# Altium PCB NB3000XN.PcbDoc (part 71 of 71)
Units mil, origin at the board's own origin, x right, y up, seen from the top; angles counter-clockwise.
Board outline 9527.56 x 6929.77 mil, 6 copper layers (Top Layer, GND+SHIELD, MidLayer1, MidLayer2, P2 - 3V3+5V0, Bottom Layer), stack 62.375 mil thick; 832 components, 1027 nets, 4655 pads, 4981 vias.
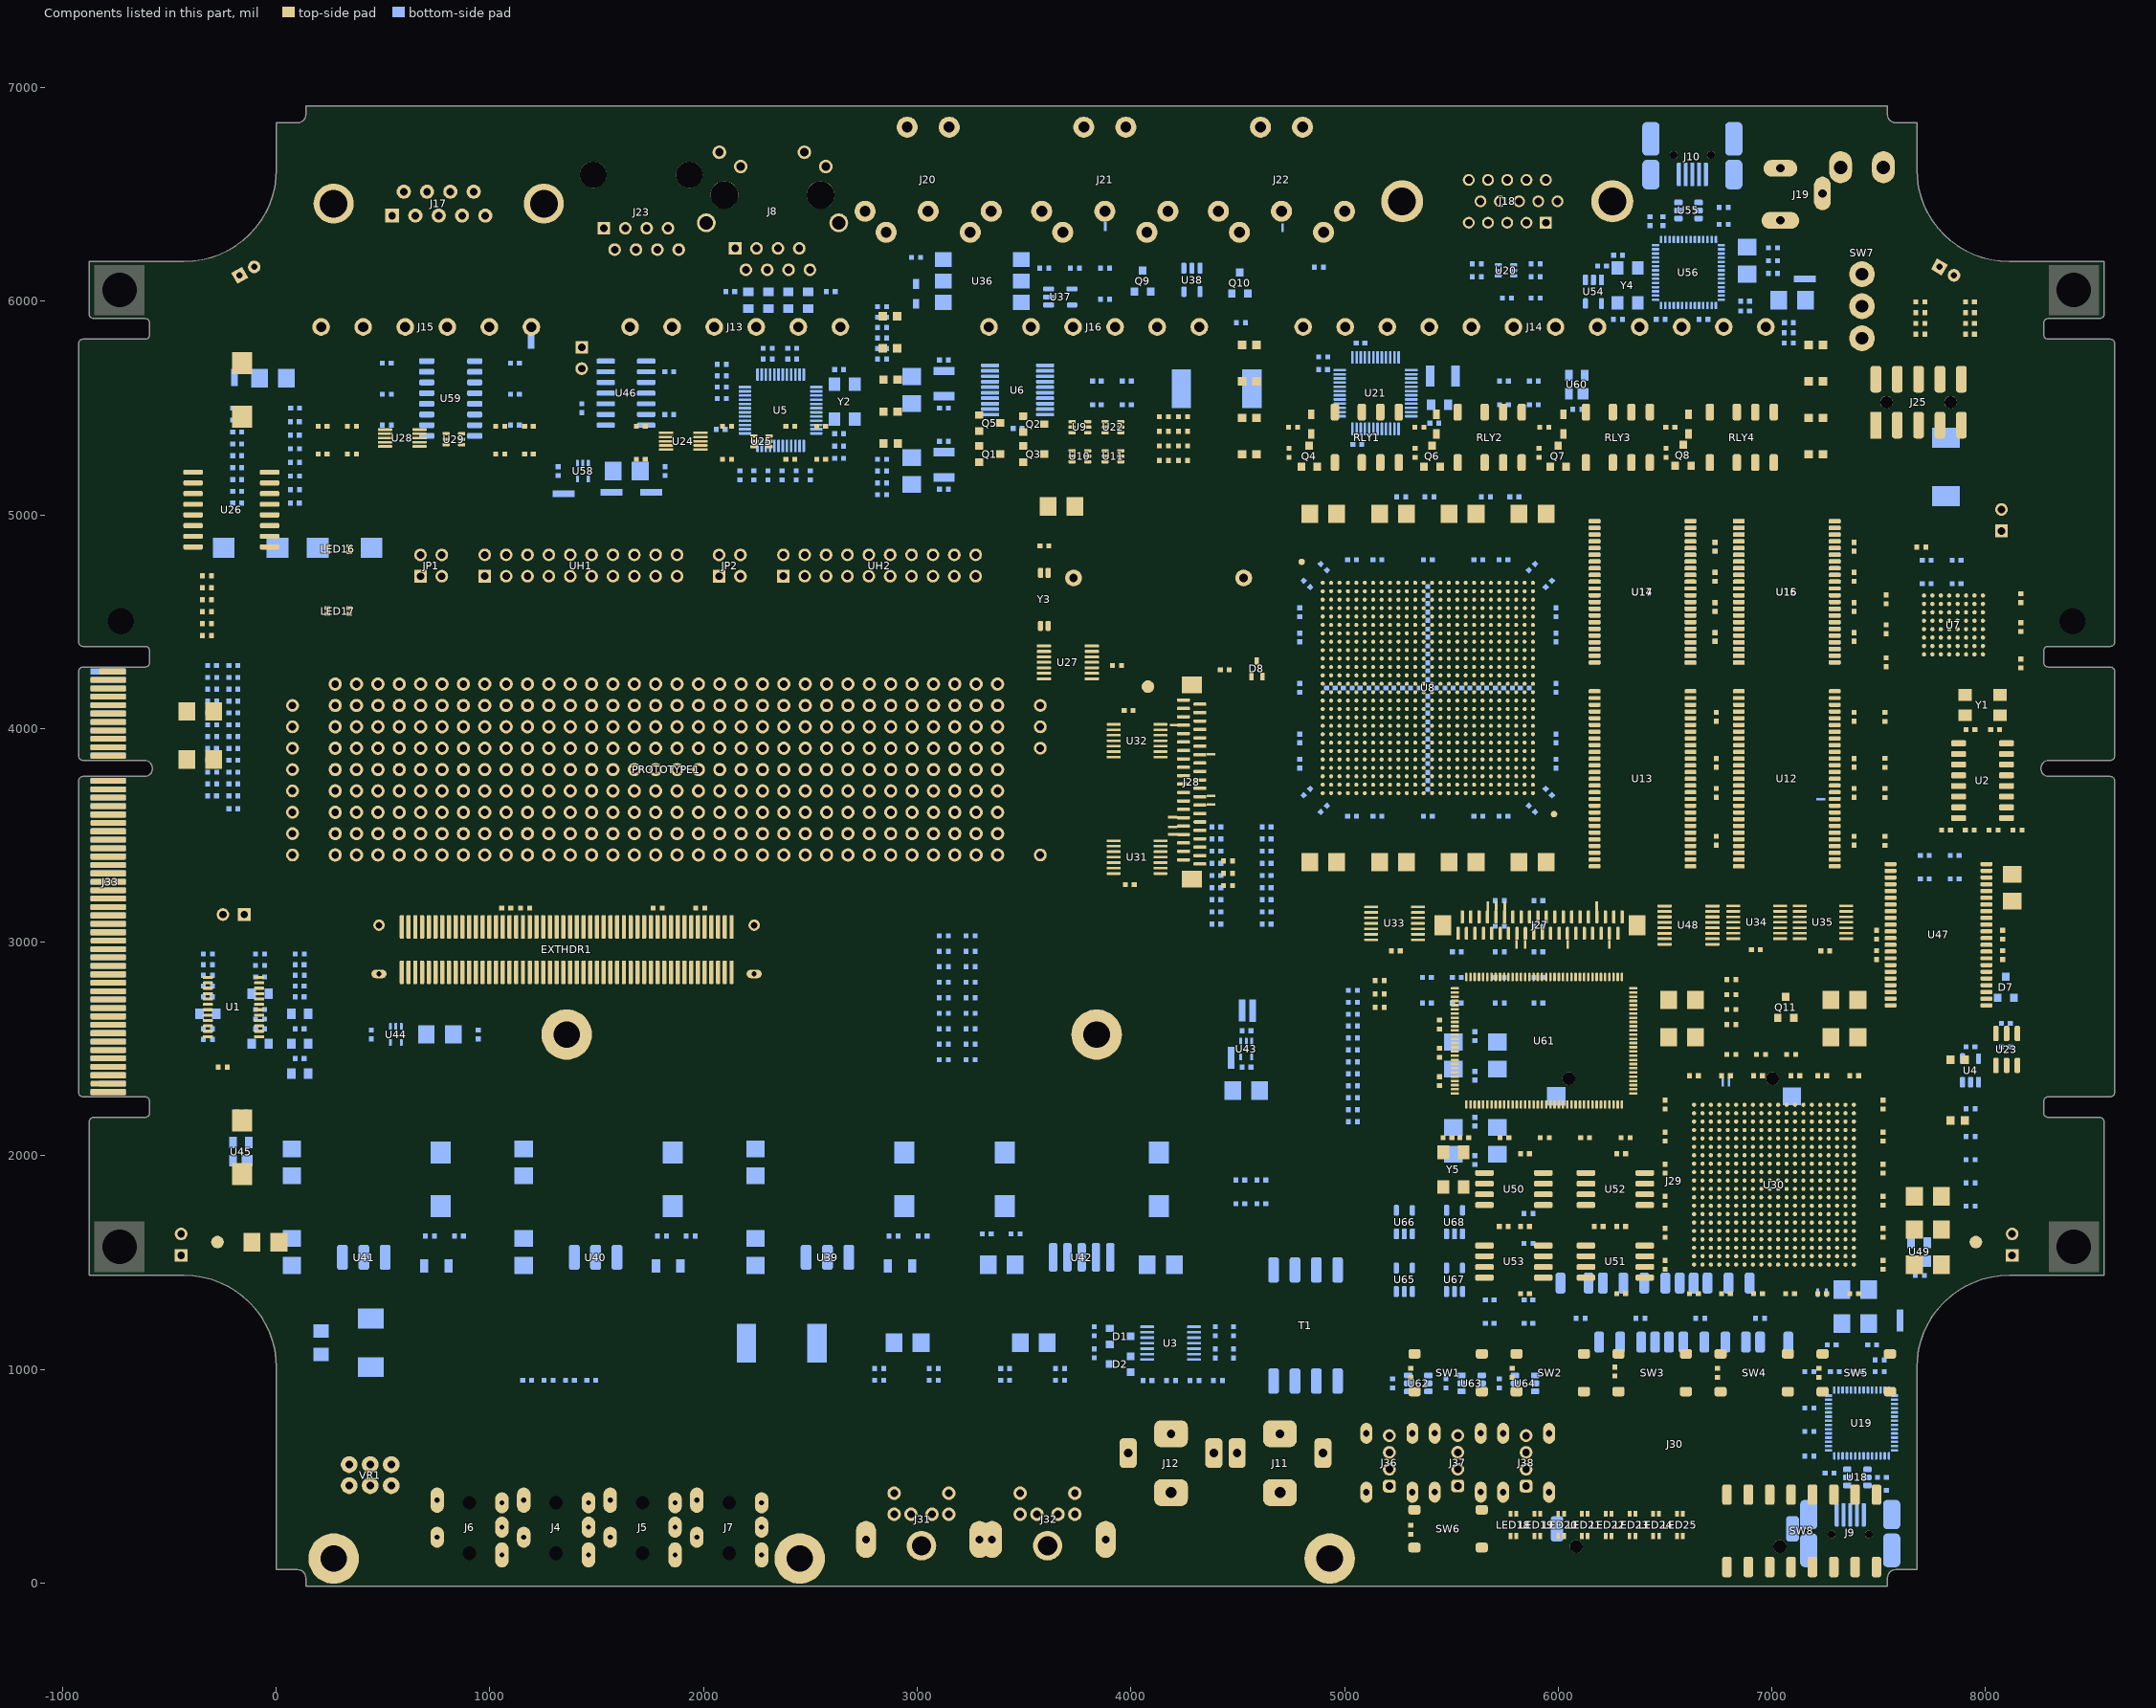
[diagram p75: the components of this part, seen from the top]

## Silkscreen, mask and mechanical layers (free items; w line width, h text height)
Top Overlay:
  drawing of 4403 lines, arcs and shapes, not listed
  text "RS232" at 604.45,6800 h90
  text "RS485" at 1610,6800 h90
  text "ETHERNET" at 2067.99,6800 h90
  text "SVGA VIDEO" at 5516.2,6800 h90
  text "HOST USB" at 6393.5,6800 h90
  text "5VDC" at 6937.6,6800 h90
  text "POWER" at 7217.89,6800 h90
  text "EIA-574" at 641.44,6725 h50
  text "10Mbps/FULL DUPLEX" at 1480,6725 h50
  text "10/100Mbps" at 2157.21,6725 h50
  text "24BIT/80MHZ" at 5623.41,6725 h50
  text "UNIVERSAL SERIAL BUS" at 6327.56,6725 h50
  text "6A MAX" at 6954.67,6725 h50
  text "ON/OFF" at 7282.58,6725 h50
  text "MIDI IN" at 2917.86,6640.83 h90
  text "MIDI THRU" at 3673.03,6640.83 h90
  text "MIDI OUT" at 4524.27,6640.83 h90
  text "MUSICAL INSTRUMENT" at 2792.21,6565.83 h50
  text "MUSICAL INSTRUMENT" at 3618.98,6565.83 h50
  text "MUSICAL INSTRUMENT" at 4445.75,6565.83 h50
  text "DIGITAL INTERFACE" at 2824.29,6520.83 h50
  text "DIGITAL INTERFACE" at 3651.07,6520.83 h50
  text "DIGITAL INTERFACE" at 4477.84,6520.83 h50
  text "5VDC" at 7170,6225 h80
  text "ADC2" at 2180.43,6180 h55
  text "ADC3" at 2377.28,6180 h55
  text "5V" at 193.92,6160 h60
  text "DAC0" at 342.27,6160 h55
  text "DAC1" at 539.12,6160 h55
  text "DAC2" at 735.97,6160 h55
  text "DAC3" at 932.82,6160 h55
  text "5V" at 1640,6160 h60
  text "ADC0" at 1786.73,6160 h55
  text "ADC1" at 1983.58,6160 h55
  text "5V" at 3319.7,6160.01 h60
  text "PWM0" at 3459.84,6160.01 h55
  text "PWM1" at 3656.69,6160.01 h55
  text "PWM2" at 3853.54,6160.01 h55
  text "PWM3" at 4050.39,6160.01 h55
  text "NC0" at 4756.79,6160 h55
  text "COM0" at 4934.36,6160 h55
  text "N00" at 5151.85,6160 h55
  text "NC1" at 5347.34,6160 h55
  text "COM1" at 5524.92,6160 h55
  text "NO1" at 5742.4,6160 h55
  text "NC2" at 5937.89,6160 h55
  text "COM2" at 6115.47,6160 h55
  text "NO2" at 6332.95,6160 h55
  text "NC3" at 6528.44,6160 h55
  text "COM3" at 6706.02,6160 h55
  text "NO3" at 6923.5,6160 h55
  text "PWM" at 4515,6040 h45
  text "RELAYS" at 7135.94,6039.99 h45
  text "RS485" at 1365,6035 h45
  text "ETHERNET STATUS" at 2797.74,6035 h45
  text "ACTIVE" at 4481.63,5980 h50
  text "ACTIVE" at 7133.34,5979.99 h50
  text "CHANNELS" at 4465.81,5940 h40
  text "CHANNELS" at 7117.52,5939.99 h40
  text "FULL DUPLEX" at 2797.74,5840 h60
  text "0" at 4640.05,5780 h50
  text "0" at 7291.76,5779.99 h50
  text "LINK" at 2797.66,5690.13 h60
  text "1" at 4644.59,5609.61 h50
  text "1" at 7296.3,5609.61 h50
  text "4x DIGITAL TO ANALOG CONVERTER" at 310,5585 h60
  text "4x ANALOG TO DIGITAL CONVERTER" at 1755,5585 h60
  text "4x PULSE WIDTH MODULATOR" at 3605,5585 h60
  text "4x ISOLATED COMMON/NORMALLY OPEN/NORMALLY CLOSED RELAYS" at 5490,5585 h50
  text "10Mbps" at 2800.53,5543.43 h60
  text "120R" at 1370,5500 h60
  text "TERM" at 1355,5445 h60
  text "2" at 4639.86,5439.23 h50
  text "2" at 7291.57,5439.22 h50
  text "100Mbps" at 2800.53,5393.64 h60
  text "ON" at 1390,5390 h60
  text "F05C" at 3776.17,5379.18 h20 r90
  text "F05C" at 3931.17,5379.18 h20 r90
  text "F05C" at 846.17,5323 h20 r90
  text "F05C" at 2286.17,5313 h20 r90
  text "84S08" at 605,5310 h24 r90
  text "84S02" at 1920,5295 h24 r90
  text "3" at 4640,5268.84 h50
  text "3" at 7291.71,5268.83 h50
  text "COLLISION" at 2800.53,5243.84 h60
  text "F05C" at 3776.17,5243 h20 r90
  text "F05C" at 3931.17,5243 h20 r90
  text "SYSTEM JTAG" at 7535,5215.53 h50
  text "PLATFORM" at 167.98,5055 h50
  text "STATUS" at 167.98,5005 h50
  text "PLATFORM" at 7621.98,4966 h50
  text "STATUS 1" at 192.18,4930 h50
  text "UPGRADE ENABLE" at 7609,4924 h35
  text "PT2300-S" at -160,4850 h50 r90
  text "2" at 583.66,4794.72 h39.37
  text "4" at 838.66,4794.72 h39.37
  text "2" at 1983.66,4794.72 h39.37
  text "4" at 2238.66,4794.72 h39.37
  text "3" at 2238.66,4694.72 h39.37
  text "1" at 593.66,4689.72 h39.37
  text "3" at 838.66,4689.72 h39.37
  text "1" at 1993.66,4689.72 h39.37
  text "STATUS 2" at 190,4640 h50
  text "32K768" at 3610,4536 h28 r90
  text "5V" at 698.66,4524.72 h70.87 r90
  text "5V" at 2098.66,4524.72 h70.87 r90
  text "3V3" at 2198.66,4509.72 h70.87 r90
  text "3V3" at 798.66,4499.72 h70.87 r90
  text "User Header A" at 1334.98,4485.26 h94.49
  text "User Header B" at 2735.98,4485.26 h94.49
  text "+" at 3783.68,4436.46 h80
  text "SRAM-256Kx16" at 6491.32,4375 h50 r90
  text "SRAM-256Kx16" at 7166.32,4375 h50 r90
  text "PCF2123" at 3735,4230 h28 r90
  text "S" at 4405.65,4118.23 h59.05
  text "GND" at -60,4095 h50
  text "32K" at 3624.39,4092.39 h50
  text "W" at 4398,4062 h53
  text "I" at 4417.2,4002.06 h59.05
  text "5V0" at -60,3995 h50
  text "GND" at 3620,3992.23 h50
  text "T" at 4406.01,3944.33 h59.05
  text "3V3" at -60,3895 h50
  text "+B" at 3640,3892.24 h50
  text "C" at 4404.55,3887.23 h59.05
  text "VHC04" at 4060,3876 h28 r90
  text "H" at 4405.9,3828.89 h59.05
  text "2V5" at -60,3795 h50
  text "&" at 4403.51,3771.12 h59.05
  text "L" at 4407.7,3713.44 h59.05
  text "1V8" at -60,3695 h50
  text "E" at 4406.66,3655.72 h59.05
  text "ICS307-02" at 8010,3625 h34 r90
  text "D" at 4405.2,3598 h59.05
  text "1V2" at -60,3595 h50
  text "DRAM-16Mx16" at 6491.32,3517.31 h50 r90
  text "DRAM-16Mx16" at 7166.32,3517.31 h50 r90
  text "I" at 4417.2,3512.21 h59.05
  text "AUL" at -60,3490 h50
  text "O" at 4402.7,3457 h59.05
  text "AUR" at -65,3395 h50
  text "BAT" at 3619.39,3392.39 h50
  text "VHC04" at 4060,3330 h28 r90
  text "GND" at 228.12,3300.23 h35
  text "1V2" at 328.12,3300.23 h35
  text "GND" at 428.12,3300.23 h35
  text "1V8" at 528.12,3300.23 h35
  text "GND" at 628.12,3300.23 h35
  text "2V5" at 728.12,3300.23 h35
  text "GND" at 2828.12,3300.23 h35
  text "3V3" at 2928.12,3300.23 h35
  text "GND" at 3028.12,3300.23 h35
  text "5V0" at 3128.12,3300.23 h35
  text "GND" at 3228.12,3300.23 h35
  text "+B" at 3328.12,3300.23 h35
  text "VHC04" at 6960,3026 h28 r90
  text "VHC04" at 7270,3026 h28 r90
  text "VHC04" at 5265,3020 h28 r90
  text "ATE" at -682.26,2995 h60
  text "XPT2406" at 6640,2992.16 h30 r90
  text "NANOCONNECT" at 1133.2,2945.23 h59.05
  text "NB3000XN.04" at 2710.45,2940 h120
  text "TOUCH SCREEN LCD IO" at 5602,2932 h59.05
  text "Xilinx Spartan 3AN" at 2710.45,2801.44 h100
  text "NB3000XN.04" at 3540,2801.44 h60
  text "SRAM-256Kx16" at 7876.32,2770 h50 r90
  text "CS4270" at -161.51,2573.97 h45 r90
  text "ISP1760" at 5808.3,2513.65 h50
  text "DS2502" at 8034,2468.01 h26
  text "PWR" at 7825,2365 h50
  text "PERIPHERAL BOARD" at 889.66,2310.23 h102.36
  text "PGM" at 7824.95,2080 h50
  text "25P80" at 5820,1775 h36 r90
  text "25P80" at 6295,1775 h36 r90
  text "25P80" at 5820,1435 h36 r90
  text "25P80" at 6295,1435 h36 r90
  text "USB2" at 5264.86,555.83 h90
  text "USB2" at 5589.86,555.04 h90
  text "USB2" at 5914.86,550.83 h90
  text "7" at 6778.45,540.42 h60
  text "6" at 6877.17,540.1 h60
  text "5" at 6978.15,540.1 h60
  text "4" at 7078,540.42 h60
  text "3" at 7177.86,540.1 h60
  text "2" at 7277.71,540.76 h60
  text "1" at 7381.56,540.42 h60
  text "0" at 7477.41,540.44 h60
  text "PORT 1" at 5288.55,490 h50
  text "PORT 2" at 5613.55,489.21 h50
  text "PORT 3" at 5938.55,485 h50
  text "HEADPHONES" at 735,480 h55
  text "LINE IN" at 1115.13,456 h60
  text "LINE OUT" at 1520.13,456 h60
  text "AMP TEST" at 1925.13,456 h60
  text "RGB USER LEDS" at 6170,424.03 h50
  text "PS2" at 2965,405 h60
  text "PS2" at 3555,405 h60
  text "L" at 816.84,404.14 h34
  text "R" at 974.84,404.14 h34
  text "L" at 1221.84,404.14 h34
  text "R" at 1379.84,404.14 h34
  text "L" at 1626.84,404.14 h34
  text "R" at 1784.84,404.14 h34
  text "L" at 2031.84,404.14 h34
  text "R" at 2189.84,404.14 h34
  text "USER DIP SWITCH" at 6853.16,219.61 h50
  text "SPDIF IN" at 4054.94,120.83 h75
  text "SPDIF OUT" at 4412.69,120.83 h75
  text "2" at 6334.69,91.1 h60
  text "7" at 5778.45,90.76 h60
  text "6" at 5890.29,90.44 h60
  text "5" at 6000.95,90.44 h60
  text "4" at 6112.19,90.76 h60
  text "3" at 6223.44,90.44 h60
  text "1" at 6450.92,90.76 h60
  text "0" at 6557.18,90.79 h60
  text "TEST/RESET" at 5320,35 h60
  text "VOLUME" at 448.47,25 h55
  text "KEYBOARD" at 2822.86,25.83 h80
  text "MOUSE" at 3474.94,25.83 h80
Bottom Overlay:
  drawing of 5178 lines, arcs and shapes, not listed
  text "2201" at 6591,6385 h28 r270
  text "F05C" at 5741,6113 h20 r270
  text "+" at -23.11,6080.76 h80 r270
  text "1G04" at 4333,6078 h28
  text "1G04" at 6212.16,6023 h28
  text "1G04" at 3663.57,5974.94 h28 r270
  text "+" at 7798.68,5943.06 h80
  text "FUSE" at 4474.37,5567.87 h80
  text "LVC244" at 3442,5503 h28 r270
  text "COMPLIANCE:" at 7334.41,5495.57 h45
  text "ISL8491IB" at 1615.05,5488.08 h28 r270
  text "RTL8201" at 2455,5470 h35
  text "CLASS 2" at 6584.41,5405.58 h40
  text "IPC-A-600G" at 7244.41,5405.57 h40
  text "HIN232ACBNZ" at 790,5380 h34 r270
  text "CLASS 2" at 6584.41,5325.58 h40
  text "TYPE 3" at 6834.41,5325.57 h40
  text "IPC-6012D" at 7244.41,5325.57 h40
  text ".Application_BuildNumber" at 4096.21,5237.03 h60
  text "AD BUILD No:" at 4460.98,5236.81 h34
  text "SRAM-256Kx16" at 6298.68,4375 h50 r270
  text "SRAM-256Kx16" at 6973.68,4375 h50 r270
  text "SD CARD" at 6794.22,3703.75 h120
  text "SDIO" at 6693.38,3510 h130
  text "SDHC" at 6717.02,3380 h130
  text "DESIGNED IN SYDNEY" at 5421,3126 h40
  text "AUSTRALIA" at 5315.43,3037 h50
  text "MANUFACTURE" at 7806.31,2995.59 h40
  text "DATE" at 7807.41,2928.79 h40
  text "1G04" at 7975.06,2393.57 h28
  text "3V3" at 266.21,2173.09 h32
  text "2V5" at 1351.21,2173 h32
  text "1V8" at 2436.14,2171 h32
  text "1V2" at 3626.14,2171 h32
  text "1G04" at 5325.06,1683.57 h28
  text "1G04" at 5560.06,1683.57 h28
  text "1G04" at 5325.06,1413.57 h28
  text "1G04" at 5560.06,1413.57 h28
  text "FUSE" at 2439.37,1097.87 h80
  text "HCU04" at 4155,1055 h28 r270
  text "2201" at 5355,975 h28 r90
  text "2201" at 5605,975 h28 r90
  text "2201" at 5855,975 h28 r90
  text "2201" at 7390,455 h28 r270
Bottom Paste:
  rectangle: 3618.53,1758.03 3918.53,2074
Top Solder:
  drawing of 369 lines, arcs and shapes, not listed
Bottom Solder:
  drawing of 373 lines, arcs and shapes, not listed
1. Boundary:
  lines w5: 4870,3670 5910,3670 5910,4710 4870,4710 4870,3670
16. Template Layer:
  lines w10: 1184,5532.61 ccw(c1184,5562.61) 1214,5562.61 ; 1214,5562.61 1214,5789.88 ccw(c1184,5789.88) 1184,5819.88 cw(c1184,5849.88) 1154,5849.88 1154,5905.73 cw(c1184,5905.73) 1184,5935.73 1264.78,5935.73 cw(c1264.78,5905.73) 1294.78,5905.73 1294.78,5502.61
